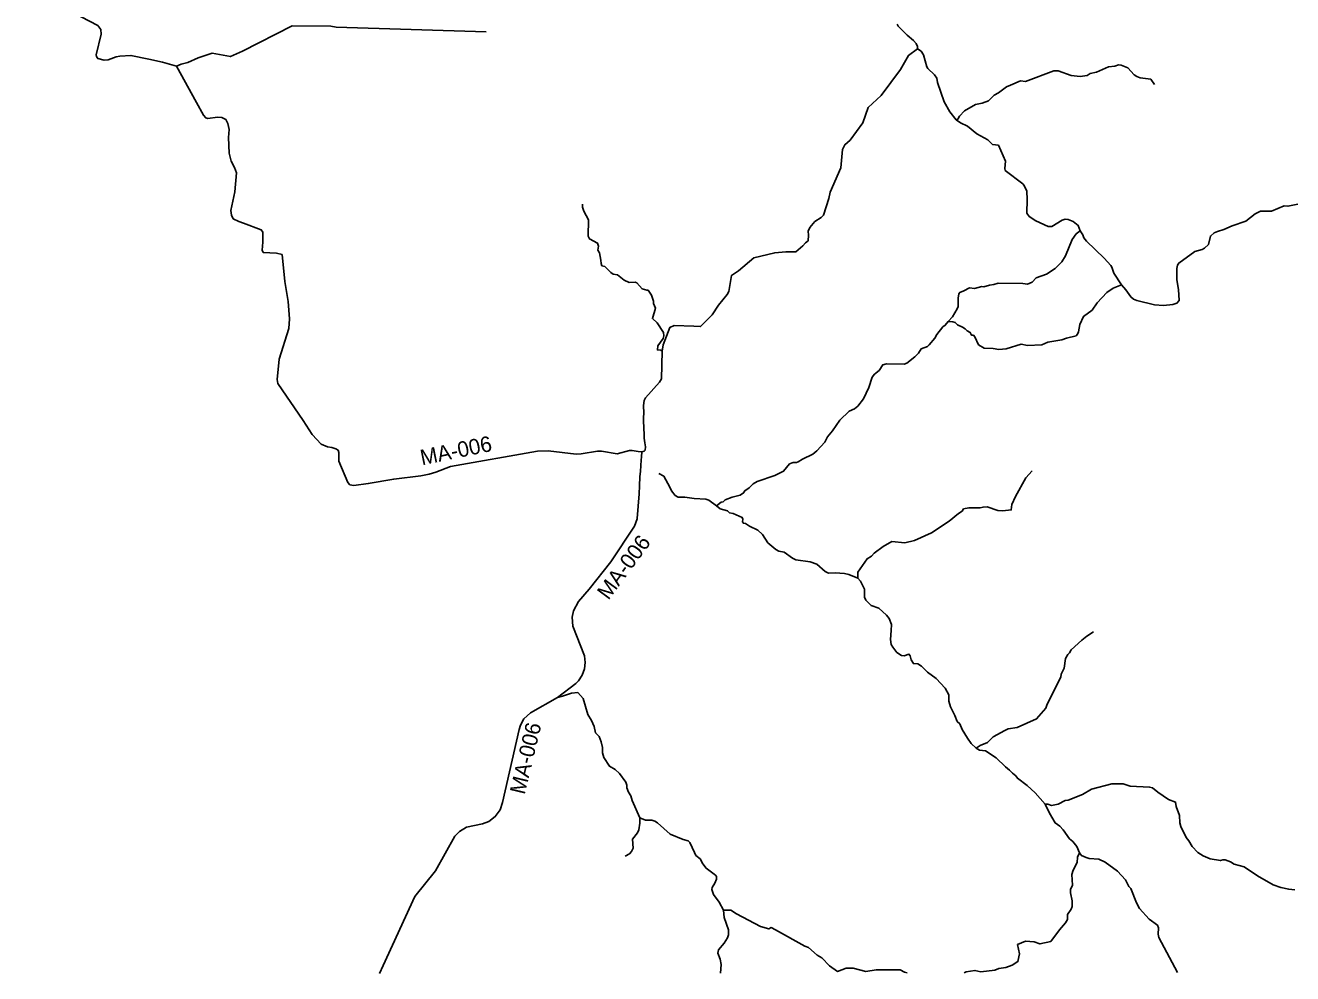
# Model space of a CAD drawing. Extents: x 332 to 501, y 9447 to 9559.
# Drawn here: x 372.71 to 403.82, y 9447.24 to 9470.52 of the extents above; entities that cross this region are included whole.
import ezdxf

# ---------------------------------------------------------------- set-up
doc = ezdxf.new("R2010")
doc.units = 0
for name, color, linetype in [('Level 2', 7, 'Continuous'), ('Level 31', 7, 'Continuous'), ('Level 4', 7, 'Continuous'), ('Level 5', 7, 'Continuous'), ('Level 6', 7, 'Continuous')]:
    doc.layers.add(name, color=color, linetype=linetype)

msp = doc.modelspace()

# ---------------------------------------------------------------- linework, layer by layer
at = {"layer": 'Level 2'}
for points in [[(372.7099, 9471.4064), (373.6851, 9470.9313), (374.4884, 9470.5166), (374.5632, 9470.4133), (374.5736, 9470.2997), (374.4497, 9469.7952), (374.4537, 9469.7528)], [(374.4537, 9469.7528), (374.4882, 9469.7036), (374.6451, 9469.6617), (374.7445, 9469.6679), (374.9386, 9469.7471), (375.0309, 9469.7581)], [(375.7436, 9469.6846), (375.303, 9469.778), (375.0309, 9469.7581)], [(376.4199, 9469.5173), (376.073, 9469.614), (375.7436, 9469.6846)], [(376.4199, 9469.5173), (376.9074, 9468.6197), (377.0815, 9468.316), (377.1381, 9468.2507), (377.186, 9468.2333), (377.4254, 9468.2638), (377.5299, 9468.2551), (377.6343, 9468.2071), (377.6778, 9468.1069), (377.7127, 9467.9631), (377.6953, 9467.7653), (377.7127, 9467.3819), (377.7605, 9467.1859), (377.8476, 9467.029), (377.8955, 9466.8939), (377.852, 9466.4304), (377.7562, 9465.9729), (377.7693, 9465.8596), (377.8128, 9465.7681), (377.9521, 9465.6984), (378.0652, 9465.6635)], [(378.0652, 9465.6635), (378.5018, 9465.4993), (378.541, 9465.4426), (378.541, 9465.1986), (378.5192, 9465.0004), (378.5497, 9464.9438), (378.8718, 9464.922), (379.011, 9464.8915), (379.0763, 9464.2292)], [(379.0763, 9464.2292), (379.159, 9463.7404), (379.1895, 9463.3134), (379.1808, 9463.0781), (378.937, 9462.327), (378.8892, 9461.8277), (378.9066, 9461.7274), (379.529, 9460.8199), (379.751, 9460.4713), (379.973, 9460.2361), (380.1297, 9460.1707), (380.2341, 9460.1576), (380.3343, 9460.1228), (380.3865, 9460.0879), (380.4082, 9460.0313), (380.4082, 9459.8221), (380.6259, 9459.2932), (380.6781, 9459.2366), (380.7739, 9459.2235), (381.1264, 9459.2671), (381.7532, 9459.3803), (382.4148, 9459.4588), (382.6237, 9459.498), (382.785, 9459.548)], [(388.3371, 9462.5183), (388.327, 9461.844), (388.275, 9461.759), (387.931, 9461.373), (387.9, 9461.307), (387.8842, 9461.1894)], [(387.8842, 9461.1894), (387.8887, 9460.9952)], [(387.8887, 9460.9952), (387.8789, 9460.8916)], [(387.8789, 9460.8916), (387.8825, 9460.8022)], [(387.8825, 9460.8022), (387.8887, 9460.6452)], [(387.8887, 9460.6452), (387.8961, 9460.4591)], [(387.8961, 9460.4591), (387.8984, 9460.3866)], [(387.8984, 9460.3866), (387.9076, 9460.3298)], [(387.9076, 9460.3298), (387.9157, 9460.2668)], [(387.9157, 9460.2668), (387.93, 9460.1713)], [(387.93, 9460.1713), (387.9217, 9460.0856)], [(386.349, 9459.997), (386.229, 9459.995), (385.541, 9460.075), (385.282, 9460.062), (383.142, 9459.687), (382.785, 9459.548)], [(387.606, 9460.078), (387.541, 9460.078), (387.237, 9460.003), (386.855, 9460.063), (386.755, 9460.064), (386.349, 9459.997)], [(387.7546, 9460.0593), (387.606, 9460.078)], [(387.839, 9460.047), (387.7546, 9460.0593)], [(387.8264, 9459.8414), (387.833, 9459.929)], [(387.833, 9459.929), (387.839, 9460.047)], [(387.8982, 9460.0621), (387.839, 9460.047)], [(387.9217, 9460.0856), (387.8982, 9460.0621)], [(387.8018, 9459.5119), (387.8058, 9459.5652)], [(387.8058, 9459.5652), (387.8166, 9459.7101)], [(387.8166, 9459.7101), (387.8264, 9459.8414)], [(387.7959, 9459.4326), (387.7858, 9459.2108)], [(387.7959, 9459.4326), (387.8018, 9459.5119)], [(387.777, 9459.017), (387.7525, 9458.7111)], [(387.7858, 9459.2108), (387.777, 9459.017)], [(387.7525, 9458.7111), (387.7286, 9458.4135)], [(387.6615, 9458.2206), (387.7281, 9458.4072)], [(387.7286, 9458.4135), (387.7281, 9458.4072)], [(386.222, 9454.362), (386.288, 9454.429), (386.379, 9454.567), (386.436, 9454.725), (386.454, 9454.876), (386.433, 9455.037), (386.148, 9455.766), (386.132, 9455.987), (386.167, 9456.148), (386.289, 9456.378), (386.548, 9456.679), (387.078, 9457.35), (387.6615, 9458.2206)], [(385.7697, 9454.0194), (386.222, 9454.362)], [(381.494, 9447.441), (382.2662, 9449.133), (382.7762, 9449.763), (383.2542, 9450.611), (383.3622, 9450.726), (383.5402, 9450.837), (383.9272, 9450.917), (384.0852, 9450.975), (384.2432, 9451.093), (384.3602, 9451.26), (384.4212, 9451.441), (384.8282, 9453.232), (384.8652, 9453.339), (384.9472, 9453.491), (385.1112, 9453.64), (385.7697, 9454.0194)], [(381.494, 9447.441), (381.4061, 9447.2392)]]:
    msp.add_lwpolyline(points, dxfattribs=at)
at = {"layer": 'Level 4'}
for points in [[(394.109, 9470.5428), (394.1333, 9470.4997), (394.3541, 9470.2723), (394.5103, 9470.1457), (394.5708, 9470.0757), (394.6076, 9469.9992), (394.6078, 9469.9446)], [(394.6078, 9469.9446), (394.388, 9469.7778), (394.1939, 9469.4315)], [(394.6078, 9469.9446), (394.6939, 9469.8823), (394.7588, 9469.7918), (394.8356, 9469.4994), (394.8639, 9469.4547), (395.0256, 9469.303), (395.0786, 9469.2189), (395.1014, 9469.112), (395.2622, 9468.6424), (395.4038, 9468.3939), (395.5601, 9468.1993)], [(394.1939, 9469.4315), (393.7141, 9468.7924), (393.3927, 9468.4987), (393.2646, 9468.1211), (392.951, 9467.6988), (392.8271, 9467.5877), (392.7626, 9467.4678), (392.7221, 9467.0202), (392.4621, 9466.4257)], [(395.5601, 9468.1993), (395.6661, 9468.1207), (395.8333, 9468.0412), (396.0617, 9467.8548), (396.3303, 9467.7096), (396.4489, 9467.5904), (396.5943, 9467.5752), (396.7652, 9467.1869), (396.7477, 9467.0043), (396.7596, 9466.9567), (397.1912, 9466.6254), (397.2259, 9466.5858), (397.2886, 9466.4489), (397.3001, 9466.241), (397.2918, 9465.9078), (397.3445, 9465.8274), (397.5117, 9465.7196), (397.8168, 9465.5798), (397.9071, 9465.5828), (398.1545, 9465.7346), (398.2337, 9465.7593), (398.302, 9465.7543), (398.4308, 9465.7013), (398.5514, 9465.6045), (398.5985, 9465.4765)], [(392.4621, 9466.4257), (392.4326, 9466.2689), (392.3005, 9465.8587), (392.2416, 9465.8014), (392.0913, 9465.7009), (391.9683, 9465.5568), (391.926, 9465.4648), (391.9341, 9465.3678), (391.9199, 9465.2302), (391.8549, 9465.1808), (391.7968, 9465.1081), (391.6214, 9464.9609), (391.3794, 9464.9609), (391.1032, 9464.9367), (390.587, 9464.8077), (390.2121, 9464.4886), (390.0425, 9464.3802), (389.978, 9463.9871), (389.9373, 9463.9078), (389.7219, 9463.6483), (389.5658, 9463.4087), (389.2843, 9463.124), (389.1162, 9463.1315)], [(388.3371, 9462.5183), (388.3061, 9462.5426), (388.2244, 9462.5507), (388.2381, 9462.6536), (388.3616, 9462.8325), (388.385, 9462.8985), (388.3722, 9462.9751), (388.2168, 9463.2115), (388.0996, 9463.318), (388.1741, 9463.5736), (388.1294, 9463.6928), (388.1294, 9463.7503), (388.0826, 9463.893), (387.9931, 9464.0186), (387.9612, 9464.0144), (387.8526, 9464.0506), (387.7206, 9464.1975), (387.6758, 9464.2103), (387.533, 9464.2018), (387.4117, 9464.2593), (387.2477, 9464.3956), (387.1348, 9464.4084), (387.0773, 9464.4467), (386.9347, 9464.5937), (386.8623, 9464.6171), (386.841, 9464.6682), (386.8388, 9464.7555), (386.8005, 9464.9301), (386.7643, 9464.9983), (386.7749, 9465.1005), (386.7536, 9465.1729), (386.5556, 9465.2751), (386.5257, 9465.339), (386.532, 9465.7458), (386.4213, 9465.9545), (386.3851, 9466.0567), (386.3872, 9466.127)], [(399.6155, 9464.1477), (399.7189, 9464.0283), (399.8411, 9463.8493), (399.9081, 9463.7969), (399.9925, 9463.7634), (400.4234, 9463.6571), (400.6476, 9463.6426), (400.8776, 9463.6644), (400.9751, 9463.7008), (401.029, 9463.7648), (401.0155, 9464.0324), (400.9762, 9464.2667), (400.9757, 9464.5456), (400.991, 9464.629), (401.0244, 9464.68), (401.4153, 9464.9626), (401.5973, 9465.0156), (401.6484, 9465.0516), (401.7507, 9465.1408), (401.7988, 9465.3434), (401.891, 9465.4213), (401.972, 9465.4607), (402.1298, 9465.5046), (402.3297, 9465.5977), (402.6637, 9465.7096), (402.8966, 9465.8916), (403.0232, 9465.9585), (403.2925, 9465.9571), (403.6042, 9466.0845), (403.6986, 9466.0764), (403.9446, 9466.1259)], [(398.5985, 9465.4765), (398.5048, 9465.3975), (398.4023, 9465.2625), (398.2367, 9464.8612), (398.1521, 9464.7154), (397.9884, 9464.55), (397.7725, 9464.4132), (397.5188, 9464.3178), (397.418, 9464.2117), (397.3099, 9464.1648), (397.1947, 9464.1828), (396.5865, 9464.1918), (396.4786, 9464.1558), (396.376, 9464.1432), (396.2392, 9464.1019), (396.1906, 9464.109), (396.0035, 9464.0551), (395.8811, 9464.0748), (395.748, 9463.9979), (395.6436, 9463.9582), (395.622, 9463.9258), (395.604, 9463.8178), (395.6022, 9463.6198), (395.5842, 9463.5586), (395.4654, 9463.3641), (395.3593, 9463.2474)], [(398.5985, 9465.4765), (398.6679, 9465.3719), (398.6912, 9465.3006), (398.7538, 9465.219), (399.1905, 9464.7998), (399.3491, 9464.6222), (399.3768, 9464.5815), (399.4277, 9464.4301), (399.6155, 9464.1477)], [(399.6155, 9464.1477), (399.4099, 9464.0641), (399.2566, 9463.9635), (399.0171, 9463.7047), (398.8925, 9463.5227), (398.6817, 9463.3741), (398.5906, 9463.1729), (398.5571, 9462.9956), (398.5331, 9462.9333), (398.4996, 9462.895), (398.2648, 9462.8423), (398.1498, 9462.7944), (397.8049, 9462.7369), (397.6564, 9462.6746), (397.3114, 9462.6602), (397.1532, 9462.689), (396.7843, 9462.5788), (396.607, 9462.5596), (396.4633, 9462.5884), (396.2463, 9462.5914)], [(389.1162, 9463.1315), (388.632, 9463.152), (388.528, 9463.102), (388.369, 9462.676), (388.3371, 9462.5183)], [(395.3593, 9463.2474), (395.289, 9463.1572), (395.2314, 9463.114), (395.0838, 9462.9286), (395.0352, 9462.8404), (394.8912, 9462.6731), (394.8516, 9462.6371), (394.7005, 9462.5741), (394.6285, 9462.4697)], [(395.3593, 9463.2474), (395.471, 9463.2413), (395.5304, 9463.2215), (395.5865, 9463.1688), (395.7152, 9463.1094), (395.7811, 9463.0698), (395.8306, 9463.017), (395.9032, 9462.9807), (395.9329, 9462.9147), (395.9791, 9462.9147), (396.0121, 9462.8685), (396.1077, 9462.6772), (396.2463, 9462.5914)], [(394.6285, 9462.4697), (394.5457, 9462.3779), (394.3424, 9462.2249), (394.283, 9462.2015), (393.8439, 9462.2069), (393.7539, 9462.1799), (393.6693, 9462.045), (393.5541, 9461.955), (393.4929, 9461.8812), (393.4137, 9461.6239), (393.2823, 9461.3485), (393.1455, 9461.1721), (393.0627, 9461.1056)], [(393.0627, 9461.1056), (392.9277, 9461.0444), (392.7046, 9460.8248), (392.5227, 9460.5657), (392.3967, 9460.4181), (392.3337, 9460.2867), (392.1375, 9460.0725), (392.0403, 9459.9934), (391.783, 9459.8674), (391.6804, 9459.799), (391.6408, 9459.7828), (391.5598, 9459.7828), (391.4663, 9459.7504), (391.3187, 9459.5776), (391.1063, 9459.4714), (390.6708, 9459.3203), (390.5755, 9459.2609), (390.4747, 9459.1619), (390.3703, 9459.0918), (390.3379, 9459.0414), (390.2515, 9458.9856), (390.0554, 9458.9352), (389.8898, 9458.8704), (389.8376, 9458.8236), (389.7872, 9458.8146), (389.6768, 9458.7215)], [(388.2605, 9459.5191), (388.3848, 9459.4509), (388.5248, 9459.1833)], [(388.5248, 9459.1833), (388.5699, 9459.0913), (388.6598, 9458.9802), (388.7339, 9458.9326), (388.8978, 9458.9326), (389.1225, 9458.9003)], [(389.6768, 9458.7215), (389.4862, 9458.8627), (389.4156, 9458.8839), (389.1225, 9458.9003)], [(392.426, 9457.0693), (392.3387, 9457.114), (392.134, 9457.2882), (391.9739, 9457.347), (391.6233, 9457.3964), (391.5432, 9457.4341), (391.3314, 9457.5824), (391.2067, 9457.6106), (391.1267, 9457.6483), (390.936, 9457.8178), (390.7995, 9458.0178), (390.6912, 9458.1261), (390.4864, 9458.2226), (390.3829, 9458.2885), (390.3335, 9458.2955), (390.3123, 9458.3308), (390.317, 9458.3991), (390.3029, 9458.4367), (390.084, 9458.5356), (389.9946, 9458.552), (389.9451, 9458.6015), (389.7663, 9458.6485), (389.6768, 9458.7215)], [(393.139, 9456.9469), (392.9201, 9457.0411), (392.8118, 9457.0622), (392.5906, 9457.0764), (392.426, 9457.0693)], [(393.9603, 9455.6642), (393.9721, 9455.8101), (393.9085, 9455.9608), (393.8473, 9456.0408), (393.6614, 9456.2079), (393.4731, 9456.2738), (393.3367, 9456.4103), (393.3037, 9456.4833), (393.3037, 9456.6739), (393.2096, 9456.8763), (393.139, 9456.9469)], [(396.0498, 9452.7767), (395.9279, 9452.8918), (395.8314, 9453.0165), (395.7066, 9453.2308), (395.6454, 9453.3743), (395.5795, 9453.4308), (395.5253, 9453.5767), (395.4171, 9453.7862), (395.3771, 9453.9274), (395.3747, 9454.0827), (395.2829, 9454.245), (395.064, 9454.4851), (394.8545, 9454.6428), (394.704, 9454.784), (394.6122, 9454.8429), (394.5086, 9454.8499), (394.4521, 9454.9464), (394.4286, 9455.0429), (394.398, 9455.0829), (394.278, 9455.0429), (394.2121, 9455.05), (394.1038, 9455.1253), (394.0003, 9455.2547), (393.965, 9455.323), (393.9485, 9455.4407), (393.9603, 9455.6642)], [(385.7697, 9454.0194), (385.8941, 9454.0476), (386.1123, 9454.127), (386.271, 9454.1369), (386.3999, 9453.993), (386.5189, 9453.6009), (386.6032, 9453.457), (386.6676, 9453.3031), (386.7073, 9453.1492), (386.7916, 9453.0599), (386.8412, 9452.9309), (386.8759, 9452.7904), (386.8759, 9452.6614), (386.9106, 9452.5422), (387.0494, 9452.3288), (387.1833, 9452.2494), (387.2973, 9452.1501), (387.4461, 9451.9367), (387.4709, 9451.8623), (387.4709, 9451.7977), (387.5105, 9451.6935), (387.575, 9451.6042), (387.6047, 9451.49), (387.7898, 9451.0606)], [(397.7401, 9451.3996), (397.4977, 9451.6749), (397.3024, 9451.8562), (397.06, 9452.035), (397.0176, 9452.0986), (396.9376, 9452.1574), (396.8693, 9452.2375), (396.7681, 9452.3151), (396.5375, 9452.5364), (396.2786, 9452.7105), (396.1326, 9452.727), (396.0498, 9452.7767)], [(397.7401, 9451.3996), (397.8035, 9451.3997), (397.8953, 9451.3644), (398.0624, 9451.3997), (398.2318, 9451.4868), (398.3071, 9451.5009), (398.6554, 9451.6374), (398.8743, 9451.7668), (399.3802, 9451.9011), (399.6556, 9451.8964), (399.8298, 9451.8446), (400.3028, 9451.8187), (400.3781, 9451.7999), (400.5052, 9451.6939), (400.7688, 9451.5174), (400.943, 9451.4492), (400.9547, 9451.3409), (401.0371, 9451.1244), (401.0442, 9450.9431), (401.0677, 9450.8514), (401.1995, 9450.583), (401.2678, 9450.503), (401.3478, 9450.3594), (401.489, 9450.2135), (401.6185, 9450.1335), (401.7903, 9450.0582), (402.0421, 9450.0135), (402.101, 9450.0323), (402.1622, 9450.03), (402.2892, 9449.9829), (402.3787, 9449.9288), (402.6258, 9449.8652), (402.9506, 9449.6416), (403.3413, 9449.4227), (403.5225, 9449.3521), (403.7179, 9449.3098), (403.8661, 9449.3003)], [(398.5829, 9450.2063), (398.5192, 9450.3617), (398.4227, 9450.4793), (398.3403, 9450.55), (398.185, 9450.7712), (398.1002, 9450.8606), (397.9896, 9450.9406), (397.8437, 9451.176), (397.7401, 9451.3996)], [(387.7898, 9451.0606), (387.794, 9450.9326), (387.7656, 9450.7673), (387.7315, 9450.6971), (387.6139, 9450.5396), (387.631, 9450.3232), (387.5892, 9450.2353), (387.538, 9450.1765), (387.4357, 9450.1252)], [(387.7898, 9451.0606), (387.9287, 9451.0052), (388.0861, 9451.0033), (388.1619, 9450.9824), (388.2264, 9450.9444), (388.5334, 9450.6613), (388.8557, 9450.5322), (388.981, 9450.5016)], [(388.981, 9450.5016), (389.0176, 9450.4608), (389.1355, 9450.2116)], [(389.1355, 9450.2116), (389.1708, 9450.141), (389.2697, 9450.061), (389.3355, 9449.9339), (389.4203, 9449.8257), (389.6484, 9449.6598), (389.6743, 9449.6245), (389.6743, 9449.5586), (389.6367, 9449.4621), (389.5684, 9449.3562), (389.5567, 9449.3021), (389.5967, 9449.1844), (389.7355, 9448.9962), (389.8461, 9448.8008)], [(395.7554, 9447.2611), (395.8008, 9447.2866), (396.0173, 9447.3196), (396.1633, 9447.2866), (396.5069, 9447.3243), (396.6057, 9447.3619), (396.7752, 9447.3902), (396.9305, 9447.4467), (397.0718, 9447.5361), (397.1118, 9447.7221), (397.0647, 9447.9527), (397.2624, 9448.0327), (397.4695, 9448.0233), (397.6132, 9447.9692), (397.8768, 9448.0304), (398.0933, 9448.3175), (398.244, 9448.487), (398.2864, 9448.5705), (398.2888, 9448.6953), (398.3806, 9448.8247), (398.4064, 9448.8906), (398.4041, 9449.0271), (398.3594, 9449.2272), (398.3664, 9449.3025), (398.4158, 9449.4108), (398.3993, 9449.6697), (398.4299, 9449.7803), (398.5288, 9449.9709), (398.5358, 9450.0956), (398.5829, 9450.2063)], [(398.5829, 9450.2063), (398.6309, 9450.1418), (398.7503, 9450.0873), (398.8178, 9450.0665), (399.0565, 9450.0458), (399.2148, 9449.9783), (399.5159, 9449.7525), (399.7158, 9449.5423), (399.7962, 9449.3814), (399.8455, 9449.3269), (399.9805, 9448.9739), (400.0584, 9448.8364), (400.2972, 9448.5794), (400.497, 9448.4289), (400.523, 9448.364), (400.5126, 9448.2057), (400.5334, 9448.1227), (400.9865, 9447.2684)], [(389.8461, 9448.8008), (389.8649, 9448.6196), (389.9684, 9448.3184), (389.9708, 9448.1912), (389.9426, 9448.1183), (389.8602, 9447.9889), (389.7214, 9447.8218), (389.7073, 9447.7418), (389.7615, 9447.5958), (389.785, 9447.4641), (389.7687, 9447.2522)], [(389.8461, 9448.8008), (390.0298, 9448.7942), (390.1616, 9448.7095), (390.757, 9448.3988), (390.9547, 9448.3376), (391.0159, 9448.3706), (391.1242, 9448.3188), (391.8445, 9447.9139), (391.9316, 9447.881), (392.1481, 9447.695), (392.2564, 9447.6268), (392.4447, 9447.4338), (392.6423, 9447.2949), (392.8565, 9447.3749), (393.0307, 9447.3749), (393.3367, 9447.2949), (393.5956, 9447.3326), (394.184, 9447.3302), (394.2852, 9447.2725), (394.3571, 9447.2591)]]:
    msp.add_lwpolyline(points, dxfattribs=at)
at = {"layer": 'Level 5'}
for points in [[(376.4199, 9469.5173), (376.5342, 9469.5667), (376.6993, 9469.608), (376.9504, 9469.7181), (377.2979, 9469.8316), (377.7451, 9469.7525), (378.0409, 9469.8867), (379.2621, 9470.5058), (380.2046, 9470.4956), (380.3422, 9470.475), (384.0194, 9470.358)], [(398.0625, 9469.4009), (398.3756, 9469.2845), (398.6016, 9469.2619), (398.7735, 9469.2891), (398.8492, 9469.3354), (398.9984, 9469.3671), (399.299, 9469.5027), (399.4505, 9469.514), (399.5432, 9469.5479), (399.6065, 9469.5434), (399.767, 9469.471), (399.9252, 9469.3037), (399.9931, 9469.2608), (400.0699, 9469.2314), (400.3321, 9469.193), (400.4226, 9469.0686)], [(395.5601, 9468.1993), (395.595, 9468.2175), (395.6391, 9468.2865), (395.7612, 9468.4153), (396.0279, 9468.5759), (396.1975, 9468.6075), (396.3535, 9468.6663), (396.4914, 9468.8042), (396.5954, 9468.8584), (396.7921, 9469.0054), (396.887, 9469.0529), (397.1334, 9469.1591), (397.2622, 9469.1387), (397.9517, 9469.4032), (398.0625, 9469.4009)]]:
    msp.add_lwpolyline(points, dxfattribs=at)
at = {"layer": 'Level 6'}
for points in [[(393.139, 9456.9469), (393.1424, 9457.0949), (393.3687, 9457.4253), (393.4764, 9457.4863), (393.541, 9457.5582), (393.7637, 9457.7269), (393.9791, 9457.8454), (394.2951, 9457.8167), (394.5358, 9457.8741), (394.9487, 9458.0573), (395.3832, 9458.3445), (395.613, 9458.5385), (395.7028, 9458.5887), (395.7387, 9458.6462), (395.8644, 9458.6713), (396.1445, 9458.6713), (396.2163, 9458.6929), (396.3168, 9458.6964), (396.5826, 9458.6103), (396.7046, 9458.5995), (396.9093, 9458.621), (396.9201, 9458.7575), (397.0135, 9458.955), (397.2684, 9459.4075), (397.4228, 9459.5834)], [(398.9297, 9455.6271), (398.7601, 9455.5275), (398.6421, 9455.428), (398.3766, 9455.192), (398.3397, 9455.1182), (398.2955, 9455.0703), (398.2365, 9454.9781), (398.207, 9454.7421), (398.1332, 9454.5872), (398.1258, 9454.5209), (397.7866, 9453.8571), (397.7571, 9453.7575), (397.5285, 9453.492), (397.0565, 9453.2818), (396.8315, 9453.245), (396.7541, 9453.2118), (396.4665, 9453.0496), (396.3264, 9452.9094), (396.1457, 9452.8357), (396.0498, 9452.7767)]]:
    msp.add_lwpolyline(points, dxfattribs=at)

# ---------------------------------------------------------------- texts
at = {"layer": 'Level 31'}
for rotation, p in [(11.60544, (382.4446, 9459.7163)), (53.54125, (387.0203, 9456.3918)), (76.54184, (384.9649, 9451.6187))]:
    msp.add_text('MA-006', height=0.38, rotation=rotation, dxfattribs=at).set_placement(p)

doc.saveas('drawing.dxf')
